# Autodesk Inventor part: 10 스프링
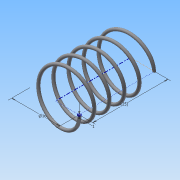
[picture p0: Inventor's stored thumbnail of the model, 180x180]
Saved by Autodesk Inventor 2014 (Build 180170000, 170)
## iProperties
Created: 2015-06
Part Number: 10 스프링
Material: 강철, 연강
Document SubType Name: Modeling
Designer: Administrator
Density: 7.86 g/cm^3
Appearance: 강철
Mass: 1.5292 g
Surface Area: 7.8715 cm^2
Volume: 0.194555 cm^3
Author: Administrator
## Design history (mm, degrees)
sketch "스케치1"
  geometry: L1 (0, 0)-(8, 0); L2 (8, 0)-(8, 14.5); L3 (8, 14.5)-(0, 14.5); L4 (0, 14.5)-(0, 0); C1 r 0.5 at (8, 0)
  constraints: 8 end point, 2 parallel, 1 centre point, 1 coincident, 1 horizontal, 1 perpendicular
  dimensions: "d0" = 16 diameter of L2 L4; "d1" = 14.5 distance of L1.end L2.end (derived); "d2" = 1 diameter of C1
feature "코일1" sketch "스케치1" pitch "d3" = 10; turns "d5" = 5; dims "d4" = 14.5 (= d1), "d6" = 0, angle "d7" = 90 deg, angle "d8" = 90 deg, "d9" = 0, "d10" = 0
sketch "스케치2"
  geometry: L1 (-8.5, 0)-(-7.5, 0) reference; 1 further point
  constraints: 1 horizontal alignment
extrude "돌출1" cut sketch "스케치2" stored distance "d11" = 10; taper "d12" = 0 deg
node "작업 평면1"
sketch "스케치3"
  geometry: L1 (8.5, 0)-(7.5, 0) reference; 1 further point
  constraints: 1 horizontal alignment
extrude "돌출2" cut sketch "스케치3" stored distance "d14" = 10; taper "d15" = 0 deg
node "솔리드1"
node "절단 모서리 투영1"
node "절단 모서리 투영2"
other parameters: "d13" = -14.5 (= -d1)
